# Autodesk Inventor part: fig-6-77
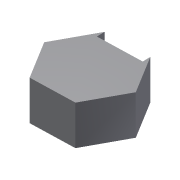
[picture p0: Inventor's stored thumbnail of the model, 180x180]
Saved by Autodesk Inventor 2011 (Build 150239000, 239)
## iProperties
Created: 2009-03
Part Number: fig-6-77
Document SubType Name: Modeling
Designer: Sham
Density: 1 g/cm^3
Author: Sham
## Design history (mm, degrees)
sketch "Sketch5"
  geometry: L1 (-5.929, 9.627)-(5.372, 9.948); L2 (5.372, 9.948)-(11.301, 0.321); L3 (11.301, 0.321)-(5.929, -9.627); L4 (5.929, -9.627)-(-5.372, -9.948); L5 (-5.372, -9.948)-(-11.301, -0.321); L6 (-11.301, -0.321)-(-5.929, 9.627); 1 further point
  constraints: 12 end point, 13 other
extrude "Extrusion3" new body sketch "Sketch5" distance "d13" = 10; taper "d14" = 0 deg
thicken "Thicken2" dims "d15" = 2, "d16" = 2
body "Solid4"
